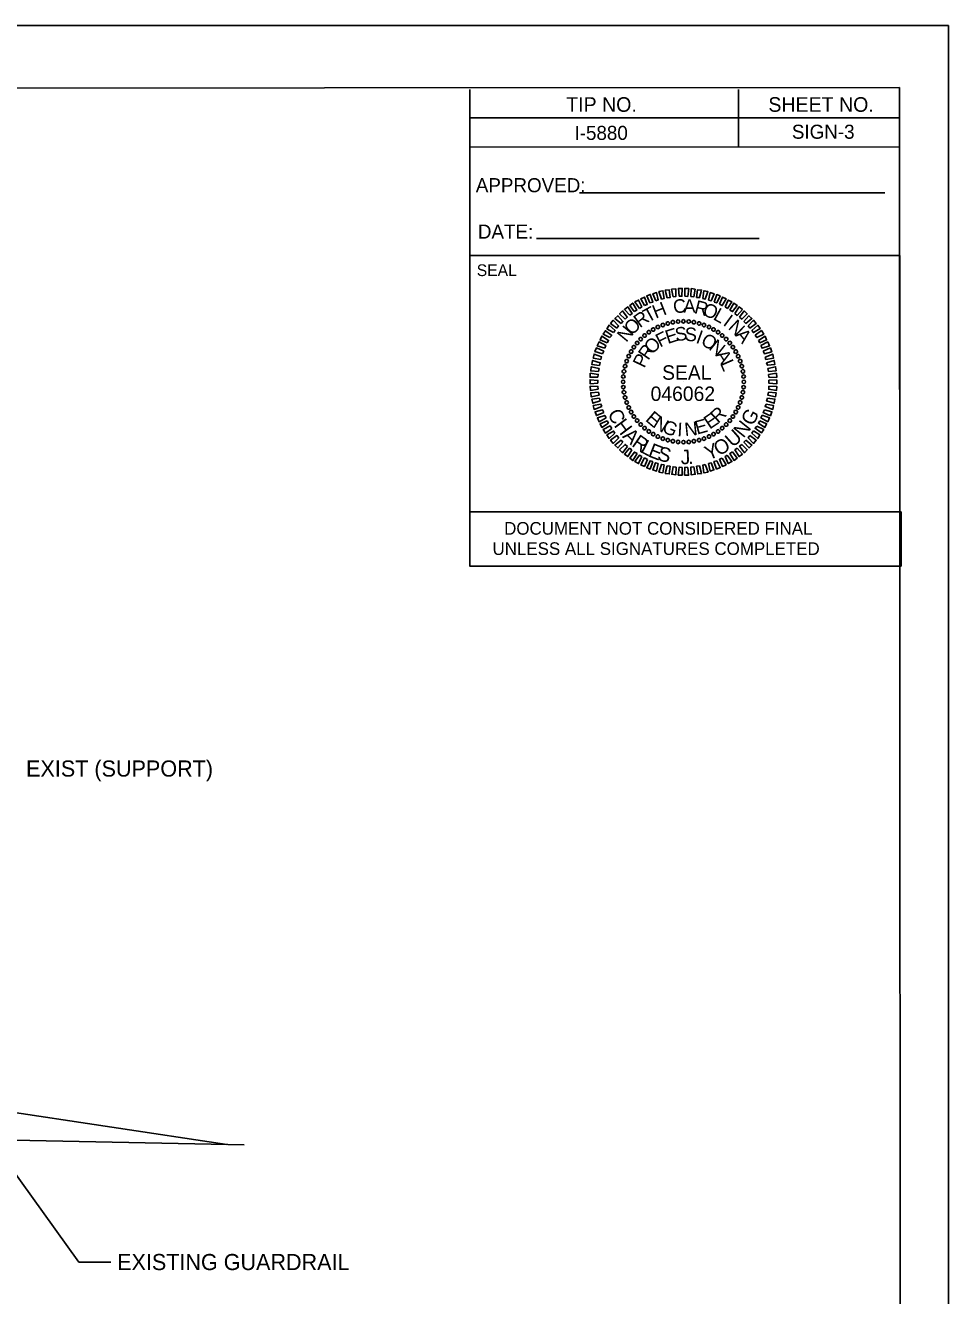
# Model space of a CAD drawing. Extents: x 1726790 to 1728895, y 539219 to 541550.
# Drawn here: x 1727517.9 to 1727598.1, y 539492 to 539602.3 of the extents above; entities that cross this region are included whole.
import ezdxf

# ---------------------------------------------------------------- set-up
doc = ezdxf.new("R2010")
doc.units = 0
for name, color, linetype in [('Default', 7, 'Continuous'), ('Old_Level_2', 7, 'Continuous'), ('Overhead Sheet Border', 7, 'Continuous'), ('Overhead Sheet Text', 7, 'Continuous'), ('Sheet Plot Border Outside CELL', 7, 'Continuous'), ('Sheet Sticker Exception Certification CELL', 7, 'Continuous'), ('Typical Pavement Slope CELL', 7, 'Continuous'), ('Typical Pavement Slope Information CELL', 7, 'Continuous')]:
    doc.layers.add(name, color=color, linetype=linetype)

msp = doc.modelspace()

# ---------------------------------------------------------------- linework, layer by layer
at = {"layer": 'Default'}
for p in [(1727512.58, 539508.79), (1727525.32, 539494.95)]:
    msp.add_line(p, (1727522.52, 539494.95), dxfattribs=at)
at = {"layer": 'Old_Level_2'}
for p, q in [((1727572.03, 539575.66), (1727572.03, 539575.66)), ((1727572.42, 539575.91), (1727572.42, 539575.91)), ((1727572.82, 539576.12), (1727572.82, 539576.12)), ((1727573.24, 539576.3), (1727573.24, 539576.3)), ((1727573.68, 539576.43), (1727573.68, 539576.43)), ((1727574.14, 539576.52), (1727574.14, 539576.52)), ((1727574.58, 539576.59), (1727574.58, 539576.59)), ((1727575.04, 539576.61), (1727575.04, 539576.61)), ((1727575.5, 539576.59), (1727575.5, 539576.59)), ((1727575.95, 539576.52), (1727575.95, 539576.52)), ((1727576.4, 539576.44), (1727576.4, 539576.44)), ((1727576.84, 539576.3), (1727576.84, 539576.3)), ((1727577.26, 539576.12), (1727577.26, 539576.12)), ((1727577.67, 539575.92), (1727577.67, 539575.92)), ((1727578.05, 539575.66), (1727578.05, 539575.66)), ((1727571.02, 539574.74), (1727571.02, 539574.74)), ((1727571.33, 539575.07), (1727571.33, 539575.07)), ((1727571.67, 539575.39), (1727571.67, 539575.39)), ((1727578.42, 539575.38), (1727578.42, 539575.38)), ((1727578.75, 539575.08), (1727578.75, 539575.08)), ((1727579.07, 539574.74), (1727579.07, 539574.74)), ((1727570.29, 539573.58), (1727570.29, 539573.58)), ((1727570.49, 539573.99), (1727570.49, 539573.99)), ((1727570.74, 539574.37), (1727570.74, 539574.37)), ((1727579.34, 539574.38), (1727579.34, 539574.38)), ((1727579.59, 539573.98), (1727579.59, 539573.98)), ((1727579.8, 539573.58), (1727579.8, 539573.58)), ((1727569.97, 539572.72), (1727569.97, 539572.72)), ((1727570.1, 539573.16), (1727570.1, 539573.16)), ((1727579.98, 539573.16), (1727579.98, 539573.16)), ((1727580.11, 539572.73), (1727580.11, 539572.73)), ((1727569.79, 539571.36), (1727569.79, 539571.36)), ((1727569.81, 539571.82), (1727569.81, 539571.82)), ((1727569.88, 539572.28), (1727569.88, 539572.28)), ((1727575.04, 539571.36), (1727575.04, 539571.36)), ((1727580.2, 539572.27), (1727580.2, 539572.27)), ((1727580.27, 539571.82), (1727580.27, 539571.82)), ((1727580.29, 539571.36), (1727580.29, 539571.36)), ((1727569.81, 539570.9), (1727569.81, 539570.9)), ((1727569.88, 539570.46), (1727569.88, 539570.46)), ((1727580.2, 539570.45), (1727580.2, 539570.45)), ((1727580.27, 539570.9), (1727580.27, 539570.9)), ((1727569.97, 539570), (1727569.97, 539570)), ((1727570.1, 539569.56), (1727570.1, 539569.56)), ((1727570.28, 539569.14), (1727570.28, 539569.14)), ((1727579.8, 539569.14), (1727579.8, 539569.14)), ((1727579.98, 539569.57), (1727579.98, 539569.57)), ((1727580.12, 539570.01), (1727580.12, 539570.01)), ((1727570.5, 539568.74), (1727570.5, 539568.74)), ((1727570.74, 539568.35), (1727570.74, 539568.35)), ((1727571.01, 539567.99), (1727571.01, 539567.99)), ((1727579.06, 539567.98), (1727579.06, 539567.98)), ((1727579.34, 539568.35), (1727579.34, 539568.35)), ((1727579.59, 539568.73), (1727579.59, 539568.73)), ((1727571.33, 539567.65), (1727571.33, 539567.65)), ((1727571.66, 539567.34), (1727571.66, 539567.34)), ((1727572.03, 539567.06), (1727572.03, 539567.06)), ((1727577.66, 539566.82), (1727577.66, 539566.82)), ((1727578.05, 539567.06), (1727578.05, 539567.06)), ((1727578.42, 539567.33), (1727578.42, 539567.33)), ((1727578.76, 539567.65), (1727578.76, 539567.65)), ((1727572.41, 539566.81), (1727572.41, 539566.81)), ((1727572.82, 539566.61), (1727572.82, 539566.61)), ((1727573.24, 539566.43), (1727573.24, 539566.43)), ((1727573.69, 539566.29), (1727573.69, 539566.29)), ((1727574.13, 539566.2), (1727574.13, 539566.2)), ((1727574.58, 539566.13), (1727574.58, 539566.13)), ((1727575.04, 539566.11), (1727575.04, 539566.11)), ((1727575.5, 539566.13), (1727575.5, 539566.13)), ((1727575.95, 539566.2), (1727575.95, 539566.2)), ((1727576.41, 539566.29), (1727576.41, 539566.29)), ((1727576.84, 539566.43), (1727576.84, 539566.43)), ((1727577.26, 539566.6), (1727577.26, 539566.6))]:
    msp.add_line(p, q, dxfattribs=at)
for points in [[(1727572.13, 539578.21), (1727571.85, 539578.82), (1727572.16, 539578.95), (1727572.39, 539578.28)], [(1727572.64, 539578.39), (1727572.39, 539579.01), (1727572.71, 539579.11), (1727572.86, 539578.47)], [(1727573.14, 539578.53), (1727572.91, 539579.19), (1727573.26, 539579.27), (1727573.36, 539578.59)], [(1727573.64, 539578.66), (1727573.46, 539579.32), (1727573.8, 539579.36), (1727573.89, 539578.69)], [(1727574.14, 539578.73), (1727574.01, 539579.4), (1727574.37, 539579.44), (1727574.39, 539578.77)], [(1727574.66, 539578.79), (1727574.6, 539579.47), (1727574.94, 539579.47), (1727574.91, 539578.79)], [(1727575.16, 539578.79), (1727575.15, 539579.47), (1727575.5, 539579.46), (1727575.41, 539578.78)], [(1727575.69, 539578.77), (1727575.72, 539579.45), (1727576.06, 539579.39), (1727575.94, 539578.73)], [(1727576.19, 539578.69), (1727576.27, 539579.36), (1727576.62, 539579.32), (1727576.44, 539578.67)], [(1727576.72, 539578.59), (1727576.82, 539579.27), (1727577.17, 539579.19), (1727576.94, 539578.54)], [(1727577.23, 539578.46), (1727577.37, 539579.11), (1727577.7, 539579.01), (1727577.45, 539578.39)], [(1727570.38, 539577.14), (1727569.92, 539577.63), (1727570.2, 539577.86), (1727570.58, 539577.28)], [(1727570.77, 539577.46), (1727570.38, 539577.98), (1727570.64, 539578.19), (1727571, 539577.59)], [(1727571.23, 539577.73), (1727570.83, 539578.29), (1727571.15, 539578.46), (1727571.42, 539577.86)], [(1727571.67, 539577.99), (1727571.33, 539578.57), (1727571.65, 539578.72), (1727571.9, 539578.08)], [(1727577.7, 539578.28), (1727577.93, 539578.94), (1727578.23, 539578.82), (1727577.94, 539578.21)], [(1727578.18, 539578.09), (1727578.43, 539578.71), (1727578.75, 539578.57), (1727578.41, 539577.98)], [(1727578.66, 539577.86), (1727578.93, 539578.46), (1727579.25, 539578.29), (1727578.86, 539577.73)], [(1727579.07, 539577.58), (1727579.43, 539578.19), (1727579.71, 539577.98), (1727579.31, 539577.46)], [(1727579.51, 539577.28), (1727579.88, 539577.86), (1727580.16, 539577.63), (1727579.71, 539577.13)], [(1727569.63, 539576.43), (1727569.09, 539576.85), (1727569.35, 539577.1), (1727569.79, 539576.6)], [(1727569.97, 539576.81), (1727569.5, 539577.26), (1727569.75, 539577.51), (1727570.16, 539576.96)], [(1727579.91, 539576.96), (1727580.33, 539577.51), (1727580.59, 539577.26), (1727580.11, 539576.81)], [(1727580.29, 539576.6), (1727580.73, 539577.1), (1727580.99, 539576.85), (1727580.45, 539576.43)], [(1727568.66, 539575.2), (1727568.07, 539575.51), (1727568.27, 539575.8), (1727568.82, 539575.39)], [(1727568.96, 539575.63), (1727568.39, 539575.97), (1727568.59, 539576.28), (1727569.1, 539575.83)], [(1727569.27, 539576.03), (1727568.72, 539576.43), (1727568.94, 539576.7), (1727569.41, 539576.22)], [(1727580.67, 539576.23), (1727581.14, 539576.71), (1727581.36, 539576.43), (1727580.82, 539576.02)], [(1727580.99, 539575.83), (1727581.49, 539576.27), (1727581.7, 539575.98), (1727581.12, 539575.63)], [(1727581.27, 539575.4), (1727581.81, 539575.81), (1727582.02, 539575.5), (1727581.42, 539575.2)], [(1727568.21, 539574.27), (1727567.56, 539574.49), (1727567.71, 539574.82), (1727568.31, 539574.5)], [(1727568.41, 539574.75), (1727567.81, 539575), (1727567.96, 539575.33), (1727568.54, 539574.95)], [(1727581.55, 539574.95), (1727582.13, 539575.32), (1727582.27, 539575), (1727581.68, 539574.75)], [(1727581.76, 539574.5), (1727582.37, 539574.83), (1727582.52, 539574.49), (1727581.87, 539574.27)], [(1727567.86, 539573.3), (1727567.21, 539573.42), (1727567.28, 539573.77), (1727567.94, 539573.52)], [(1727568.01, 539573.8), (1727567.36, 539573.98), (1727567.49, 539574.3), (1727568.12, 539574.02)], [(1727581.96, 539574.01), (1727582.59, 539574.3), (1727582.71, 539573.97), (1727582.07, 539573.8)], [(1727582.14, 539573.51), (1727582.8, 539573.77), (1727582.87, 539573.42), (1727582.21, 539573.3)], [(1727567.66, 539572.26), (1727566.99, 539572.31), (1727567.03, 539572.67), (1727567.71, 539572.51)], [(1727567.74, 539572.79), (1727567.09, 539572.86), (1727567.15, 539573.22), (1727567.82, 539573.01)], [(1727582.27, 539573.01), (1727582.93, 539573.22), (1727582.99, 539572.87), (1727582.34, 539572.8)], [(1727582.37, 539572.51), (1727583.05, 539572.67), (1727583.09, 539572.32), (1727582.42, 539572.26)], [(1727567.62, 539571.23), (1727566.94, 539571.19), (1727566.93, 539571.54), (1727567.61, 539571.48)], [(1727567.62, 539571.76), (1727566.94, 539571.76), (1727566.95, 539572.11), (1727567.64, 539572.01)], [(1727582.44, 539572.01), (1727583.12, 539572.11), (1727583.15, 539571.75), (1727582.47, 539571.76)], [(1727582.46, 539571.49), (1727583.14, 539571.53), (1727583.15, 539571.18), (1727582.47, 539571.24)], [(1727567.64, 539570.71), (1727566.96, 539570.61), (1727566.93, 539570.97), (1727567.61, 539570.96)], [(1727567.71, 539570.21), (1727567.03, 539570.05), (1727566.99, 539570.41), (1727567.66, 539570.46)], [(1727582.42, 539570.47), (1727583.09, 539570.41), (1727583.05, 539570.06), (1727582.37, 539570.21)], [(1727582.46, 539570.97), (1727583.14, 539570.96), (1727583.13, 539570.61), (1727582.45, 539570.72)], [(1727567.81, 539569.71), (1727567.16, 539569.5), (1727567.09, 539569.85), (1727567.74, 539569.93)], [(1727567.95, 539569.21), (1727567.28, 539568.96), (1727567.21, 539569.3), (1727567.87, 539569.43)], [(1727582.22, 539569.43), (1727582.87, 539569.3), (1727582.8, 539568.96), (1727582.14, 539569.21)], [(1727582.35, 539569.93), (1727582.99, 539569.86), (1727582.93, 539569.5), (1727582.27, 539569.71)], [(1727568.12, 539568.71), (1727567.49, 539568.43), (1727567.37, 539568.75), (1727568.01, 539568.93)], [(1727568.32, 539568.22), (1727567.71, 539567.9), (1727567.57, 539568.23), (1727568.21, 539568.45)], [(1727568.54, 539567.78), (1727567.96, 539567.4), (1727567.81, 539567.72), (1727568.41, 539567.97)], [(1727581.67, 539567.97), (1727582.27, 539567.72), (1727582.12, 539567.4), (1727581.55, 539567.77)], [(1727581.87, 539568.46), (1727582.52, 539568.23), (1727582.37, 539567.9), (1727581.77, 539568.23)], [(1727582.07, 539568.92), (1727582.72, 539568.75), (1727582.59, 539568.42), (1727581.96, 539568.7)], [(1727568.82, 539567.32), (1727568.27, 539566.91), (1727568.06, 539567.22), (1727568.67, 539567.53)], [(1727569.09, 539566.9), (1727568.59, 539566.45), (1727568.39, 539566.75), (1727568.97, 539567.09)], [(1727581.12, 539567.1), (1727581.69, 539566.75), (1727581.5, 539566.44), (1727580.99, 539566.89)], [(1727581.43, 539567.52), (1727582.02, 539567.22), (1727581.81, 539566.92), (1727581.26, 539567.33)], [(1727569.42, 539566.49), (1727568.94, 539566.02), (1727568.72, 539566.29), (1727569.27, 539566.7)], [(1727569.79, 539566.12), (1727569.35, 539565.63), (1727569.09, 539565.87), (1727569.63, 539566.29)], [(1727570.17, 539565.76), (1727569.75, 539565.21), (1727569.5, 539565.46), (1727569.97, 539565.92)], [(1727580.11, 539565.92), (1727580.58, 539565.47), (1727580.34, 539565.21), (1727579.92, 539565.77)], [(1727580.45, 539566.29), (1727580.99, 539565.87), (1727580.74, 539565.63), (1727580.29, 539566.12)], [(1727580.81, 539566.69), (1727581.36, 539566.29), (1727581.14, 539566.02), (1727580.67, 539566.5)], [(1727570.57, 539565.45), (1727570.2, 539564.87), (1727569.92, 539565.09), (1727570.37, 539565.59)], [(1727571.01, 539565.14), (1727570.65, 539564.53), (1727570.38, 539564.74), (1727570.78, 539565.26)], [(1727571.42, 539564.87), (1727571.15, 539564.27), (1727570.83, 539564.44), (1727571.22, 539564.99)], [(1727571.91, 539564.63), (1727571.66, 539564.01), (1727571.33, 539564.15), (1727571.67, 539564.75)], [(1727578.41, 539564.74), (1727578.75, 539564.16), (1727578.43, 539564.01), (1727578.18, 539564.64)], [(1727578.85, 539565), (1727579.25, 539564.44), (1727578.93, 539564.27), (1727578.66, 539564.87)], [(1727579.31, 539565.27), (1727579.71, 539564.74), (1727579.44, 539564.54), (1727579.08, 539565.14)], [(1727579.7, 539565.59), (1727580.16, 539565.09), (1727579.88, 539564.87), (1727579.51, 539565.45)], [(1727572.38, 539564.44), (1727572.15, 539563.78), (1727571.86, 539563.9), (1727572.14, 539564.51)], [(1727572.85, 539564.26), (1727572.71, 539563.61), (1727572.38, 539563.71), (1727572.63, 539564.33)], [(1727573.36, 539564.14), (1727573.26, 539563.46), (1727572.91, 539563.53), (1727573.14, 539564.19)], [(1727573.89, 539564.03), (1727573.81, 539563.36), (1727573.46, 539563.41), (1727573.64, 539564.06)], [(1727574.4, 539563.96), (1727574.37, 539563.28), (1727574.02, 539563.33), (1727574.14, 539563.99)], [(1727574.92, 539563.93), (1727574.93, 539563.25), (1727574.59, 539563.26), (1727574.67, 539563.94)], [(1727575.42, 539563.93), (1727575.49, 539563.25), (1727575.14, 539563.26), (1727575.17, 539563.94)], [(1727575.94, 539563.99), (1727576.07, 539563.33), (1727575.72, 539563.28), (1727575.69, 539563.96)], [(1727576.44, 539564.07), (1727576.62, 539563.4), (1727576.28, 539563.36), (1727576.19, 539564.03)], [(1727576.94, 539564.19), (1727577.18, 539563.53), (1727576.82, 539563.45), (1727576.73, 539564.13)], [(1727577.44, 539564.33), (1727577.69, 539563.71), (1727577.37, 539563.61), (1727577.23, 539564.26)], [(1727577.95, 539564.51), (1727578.24, 539563.91), (1727577.92, 539563.78), (1727577.69, 539564.44)]]:
    msp.add_lwpolyline(points, close=True, dxfattribs=at)
for centre, major_axis in [((1727574.58, 539576.59), (-0.013, 0.15)), ((1727575.04, 539576.61), (0, 0.151)), ((1727575.5, 539576.59), (0.013, 0.15)), ((1727572.03, 539575.66), (-0.086, 0.123)), ((1727572.42, 539575.9), (-0.075, 0.13)), ((1727572.82, 539576.12), (-0.064, 0.136)), ((1727573.25, 539576.29), (-0.052, 0.142)), ((1727573.68, 539576.43), (-0.039, 0.145)), ((1727574.13, 539576.53), (-0.026, 0.148)), ((1727575.95, 539576.53), (0.026, 0.148)), ((1727576.4, 539576.43), (0.039, 0.145)), ((1727576.83, 539576.29), (0.052, 0.142)), ((1727577.26, 539576.12), (0.064, 0.136)), ((1727577.66, 539575.9), (0.075, 0.13)), ((1727578.05, 539575.66), (0.086, 0.123)), ((1727570.74, 539574.37), (-0.123, 0.086)), ((1727571.02, 539574.73), (-0.115, 0.097)), ((1727571.33, 539575.07), (-0.106, 0.106)), ((1727571.67, 539575.38), (-0.097, 0.115)), ((1727578.41, 539575.38), (0.097, 0.115)), ((1727578.75, 539575.07), (0.106, 0.106)), ((1727579.06, 539574.73), (0.115, 0.097)), ((1727579.34, 539574.37), (0.123, 0.086)), ((1727570.29, 539573.58), (-0.136, 0.064)), ((1727570.5, 539573.98), (-0.13, 0.075)), ((1727579.58, 539573.98), (0.13, 0.075)), ((1727579.79, 539573.58), (0.136, 0.064)), ((1727569.88, 539572.27), (-0.148, 0.026)), ((1727569.97, 539572.72), (-0.145, 0.039)), ((1727570.11, 539573.16), (-0.142, 0.052)), ((1727579.97, 539573.16), (0.142, 0.052)), ((1727580.11, 539572.72), (0.145, 0.039)), ((1727580.21, 539572.27), (0.148, 0.026)), ((1727569.8, 539571.36), (-0.151, 0)), ((1727569.82, 539571.82), (-0.15, 0.013)), ((1727580.27, 539571.82), (0.15, 0.013)), ((1727580.29, 539571.36), (0.151, 0)), ((1727569.82, 539570.9), (-0.15, -0.013)), ((1727569.88, 539570.45), (-0.148, -0.026)), ((1727569.97, 539570), (-0.145, -0.039)), ((1727580.11, 539570), (0.145, -0.039)), ((1727580.21, 539570.45), (0.148, -0.026)), ((1727580.27, 539570.9), (0.15, -0.013)), ((1727570.11, 539569.57), (-0.142, -0.052)), ((1727570.29, 539569.14), (-0.136, -0.064)), ((1727579.79, 539569.14), (0.136, -0.064)), ((1727579.97, 539569.57), (0.142, -0.052)), ((1727570.5, 539568.74), (-0.13, -0.075)), ((1727570.74, 539568.35), (-0.123, -0.086)), ((1727571.02, 539567.99), (-0.115, -0.097)), ((1727579.06, 539567.99), (0.115, -0.097)), ((1727579.34, 539568.35), (0.123, -0.086)), ((1727579.58, 539568.74), (0.13, -0.075)), ((1727571.33, 539567.65), (-0.106, -0.106)), ((1727571.67, 539567.34), (-0.097, -0.115)), ((1727572.03, 539567.06), (-0.086, -0.123)), ((1727572.42, 539566.82), (-0.075, -0.13)), ((1727577.66, 539566.82), (0.075, -0.13)), ((1727578.05, 539567.06), (0.086, -0.123)), ((1727578.41, 539567.34), (0.097, -0.115)), ((1727578.75, 539567.65), (0.106, -0.106)), ((1727572.82, 539566.61), (-0.064, -0.136)), ((1727573.25, 539566.43), (-0.052, -0.142)), ((1727573.68, 539566.3), (-0.039, -0.145)), ((1727574.13, 539566.2), (-0.026, -0.148)), ((1727574.58, 539566.14), (-0.013, -0.15)), ((1727575.04, 539566.12), (0, -0.151)), ((1727575.5, 539566.14), (0.013, -0.15)), ((1727575.95, 539566.2), (0.026, -0.148)), ((1727576.4, 539566.3), (0.039, -0.145)), ((1727576.83, 539566.43), (0.052, -0.142)), ((1727577.26, 539566.61), (0.064, -0.136))]:
    msp.add_ellipse(centre, major_axis=major_axis, ratio=0.999708, dxfattribs=at)
at = {"layer": 'Overhead Sheet Border'}
for p, q in [((1727556.49, 539591.75), (1727556.49, 539596.73)), ((1727579.82, 539591.74), (1727579.82, 539596.73)), ((1727556.49, 539594.29), (1727579.82, 539594.29)), ((1727579.82, 539594.29), (1727593.85, 539594.29)), ((1727556.49, 539591.75), (1727593.85, 539591.74)), ((1727556.49, 539582.32), (1727556.49, 539591.75))]:
    msp.add_line(p, q, dxfattribs=at)
for points in [[(1727593.82, 539596.91), (1727294.08, 539596.75), (1727294.19, 539386.93), (1727593.93, 539387.09)], [(1727556.49, 539582.32), (1727593.85, 539582.32), (1727593.85, 539560.06), (1727556.49, 539560.06)]]:
    msp.add_lwpolyline(points, close=True, dxfattribs=at)
at = {"layer": 'Overhead Sheet Text'}
for p, q in [((1727566.02, 539587.77), (1727592.52, 539587.77)), ((1727562.29, 539583.79), (1727581.63, 539583.79))]:
    msp.add_line(p, q, dxfattribs=at)
at = {"layer": 'Sheet Plot Border Outside CELL'}
msp.add_lwpolyline([(1727598.07, 539602.3), (1727261.51, 539602.3), (1727261.51, 539383.13), (1727598.07, 539383.13)], close=True, dxfattribs=at)
at = {"layer": 'Sheet Sticker Exception Certification CELL'}
for p, q in [((1727579.82, 539591.74), (1727579.82, 539596.73)), ((1727593.85, 539596.73), (1727593.85, 539596.73)), ((1727593.85, 539596.73), (1727593.85, 539596.73)), ((1727593.85, 539596.73), (1727593.85, 539596.73)), ((1727593.85, 539596.73), (1727593.85, 539596.73)), ((1727593.85, 539596.73), (1727593.85, 539596.73)), ((1727593.85, 539596.73), (1727593.85, 539596.73)), ((1727593.85, 539596.73), (1727593.85, 539596.73)), ((1727593.85, 539596.73), (1727593.85, 539596.73))]:
    msp.add_line(p, q, dxfattribs=at)
msp.add_lwpolyline([(1727556.49, 539560.06), (1727593.95, 539560.06), (1727593.95, 539555.36), (1727556.49, 539555.36)], close=True, dxfattribs=at)
at = {"layer": 'Typical Pavement Slope CELL'}
for p, q in [((1727510.6, 539508.89), (1727535.4, 539505.14)), ((1727536.9, 539505.12), (1727484.18, 539506.17))]:
    msp.add_line(p, q, dxfattribs=at)

# ---------------------------------------------------------------- texts
at = {"layer": 'Default'}
for s, rotation, p in [('C', 297.1998, (1727568.42, 539568.62)), ('H', 306.6436, (1727568.96, 539567.57)), ('N', 51.2288, (1727580.25, 539566.42)), ('G', 61.7997, (1727581.06, 539567.46)), ('A', 316.4834, (1727569.69, 539566.58)), ('U', 41.4347, (1727579.33, 539565.61)), ('R', 325.196, (1727570.48, 539565.83)), ('L', 332.5683, (1727571.23, 539565.29)), ('E', 338.7524, (1727571.9, 539564.91)), ('S', 345.7591, (1727572.71, 539564.58)), ('Y', 22.2425, (1727577.2, 539564.52)), ('O', 30.0413, (1727578.11, 539564.88)), ('J', 3.0321, (1727574.83, 539564.19)), ('.', 8.2139, (1727575.48, 539564.2))]:
    msp.add_text(s, height=1.25, rotation=rotation, dxfattribs=at).set_placement(p)
msp.add_text('EXISTING GUARDRAIL', height=1.3999, dxfattribs=at).set_placement((1727525.86, 539494.25))
at = {"layer": 'Old_Level_2'}
for s, height, rotation, p in [('T', 1.18, 28.8197, (1727571.96, 539576.47)), ('H', 1.18, 21.6194, (1727572.63, 539576.83)), ('C', 1.18, 7.2198, (1727574.22, 539577.28)), ('A', 1.18, 0.0203, (1727575.04, 539577.35)), ('R', 1.18, 345.6211, (1727575.92, 539577.33)), ('O', 1.18, 338.4211, (1727576.62, 539577.18)), ('O', 1.18, 43.2217, (1727570.55, 539575.34)), ('R', 1.18, 36.0205, (1727571.26, 539576)), ('L', 1.18, 331.2208, (1727577.55, 539576.81)), ('I', 1.18, 324.0201, (1727578.41, 539576.33)), ('N', 1.18, 316.8189, (1727578.86, 539576.01)), ('N', 1.18, 50.4235, (1727570.08, 539574.73)), ('F', 1.18, 26.967, (1727573.01, 539574.32)), ('E', 1.18, 17.611, (1727573.68, 539574.64)), ('S', 1.18, 8.2556, (1727574.39, 539574.87)), ('S', 1.18, 358.9004, (1727575.15, 539574.9)), ('I', 1.18, 340.1896, (1727576.05, 539574.77)), ('A', 1.18, 309.6171, (1727579.49, 539575.4)), ('R', 1.18, 55.0396, (1727571.98, 539573.17)), ('O', 1.18, 45.6812, (1727572.33, 539573.69)), ('O', 1.18, 330.8335, (1727576.47, 539574.63)), ('N', 1.18, 321.4766, (1727577.18, 539574.22)), ('P', 1.18, 64.3989, (1727571.65, 539572.49)), ('A', 1.18, 302.7602, (1727577.78, 539573.69)), ('SEAL', 1.254, 360, (1727573.19, 539571.54)), ('L', 1.18, 293.4008, (1727578.2, 539572.98)), ('046062', 1.255, 360, (1727572.19, 539569.7)), ('R', 1.18, 43.4814, (1727578.05, 539567.7)), ('E', 1.18, 319.2769, (1727571.67, 539568.03)), ('N', 1.18, 328.6339, (1727572.31, 539567.48)), ('G', 1.18, 337.9902, (1727573.11, 539567.02)), ('E', 1.18, 15.4117, (1727576.22, 539566.77)), ('E', 1.18, 34.1241, (1727577.32, 539567.2)), ('I', 1.18, 356.7012, (1727574.49, 539566.65)), ('N', 1.18, 6.0564, (1727575.19, 539566.63))]:
    msp.add_text(s, height=height, rotation=rotation, dxfattribs=at).set_placement(p)
at = {"layer": 'Overhead Sheet Text'}
for s, height, p in [('TIP NO.', 1.27, (1727564.86, 539594.8)), ('SHEET NO.', 1.27, (1727582.42, 539594.8)), ('I-5880', 1.221, (1727565.58, 539592.36)), ('SIGN-3', 1.221, (1727584.46, 539592.46)), ('APPROVED:', 1.221, (1727557.01, 539587.82)), ('DATE:', 1.221, (1727557.19, 539583.79)), ('SEAL', 1.018, (1727557.09, 539580.54))]:
    msp.add_text(s, height=height, rotation=359.9949, dxfattribs=at).set_placement(p)
at = {"layer": 'Sheet Sticker Exception Certification CELL'}
for s, p in [('DOCUMENT NOT CONSIDERED FINAL', (1727559.47, 539558.09)), ('UNLESS ALL SIGNATURES COMPLETED', (1727558.46, 539556.33))]:
    msp.add_text(s, height=1.0989, dxfattribs=at).set_placement(p)
at = {"layer": 'Typical Pavement Slope Information CELL'}
msp.add_text('EXIST (SUPPORT)', height=1.401, dxfattribs=at).set_placement((1727517.95, 539537.09))

doc.saveas('drawing.dxf')
